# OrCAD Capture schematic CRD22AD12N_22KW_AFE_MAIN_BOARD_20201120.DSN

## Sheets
1 P1 Input and EMI filter: size A2; title: 22kW Three Phase Bi-directional AFE ACDC Main Board; rev: 0v1; note: P/N: CRD22AD12N
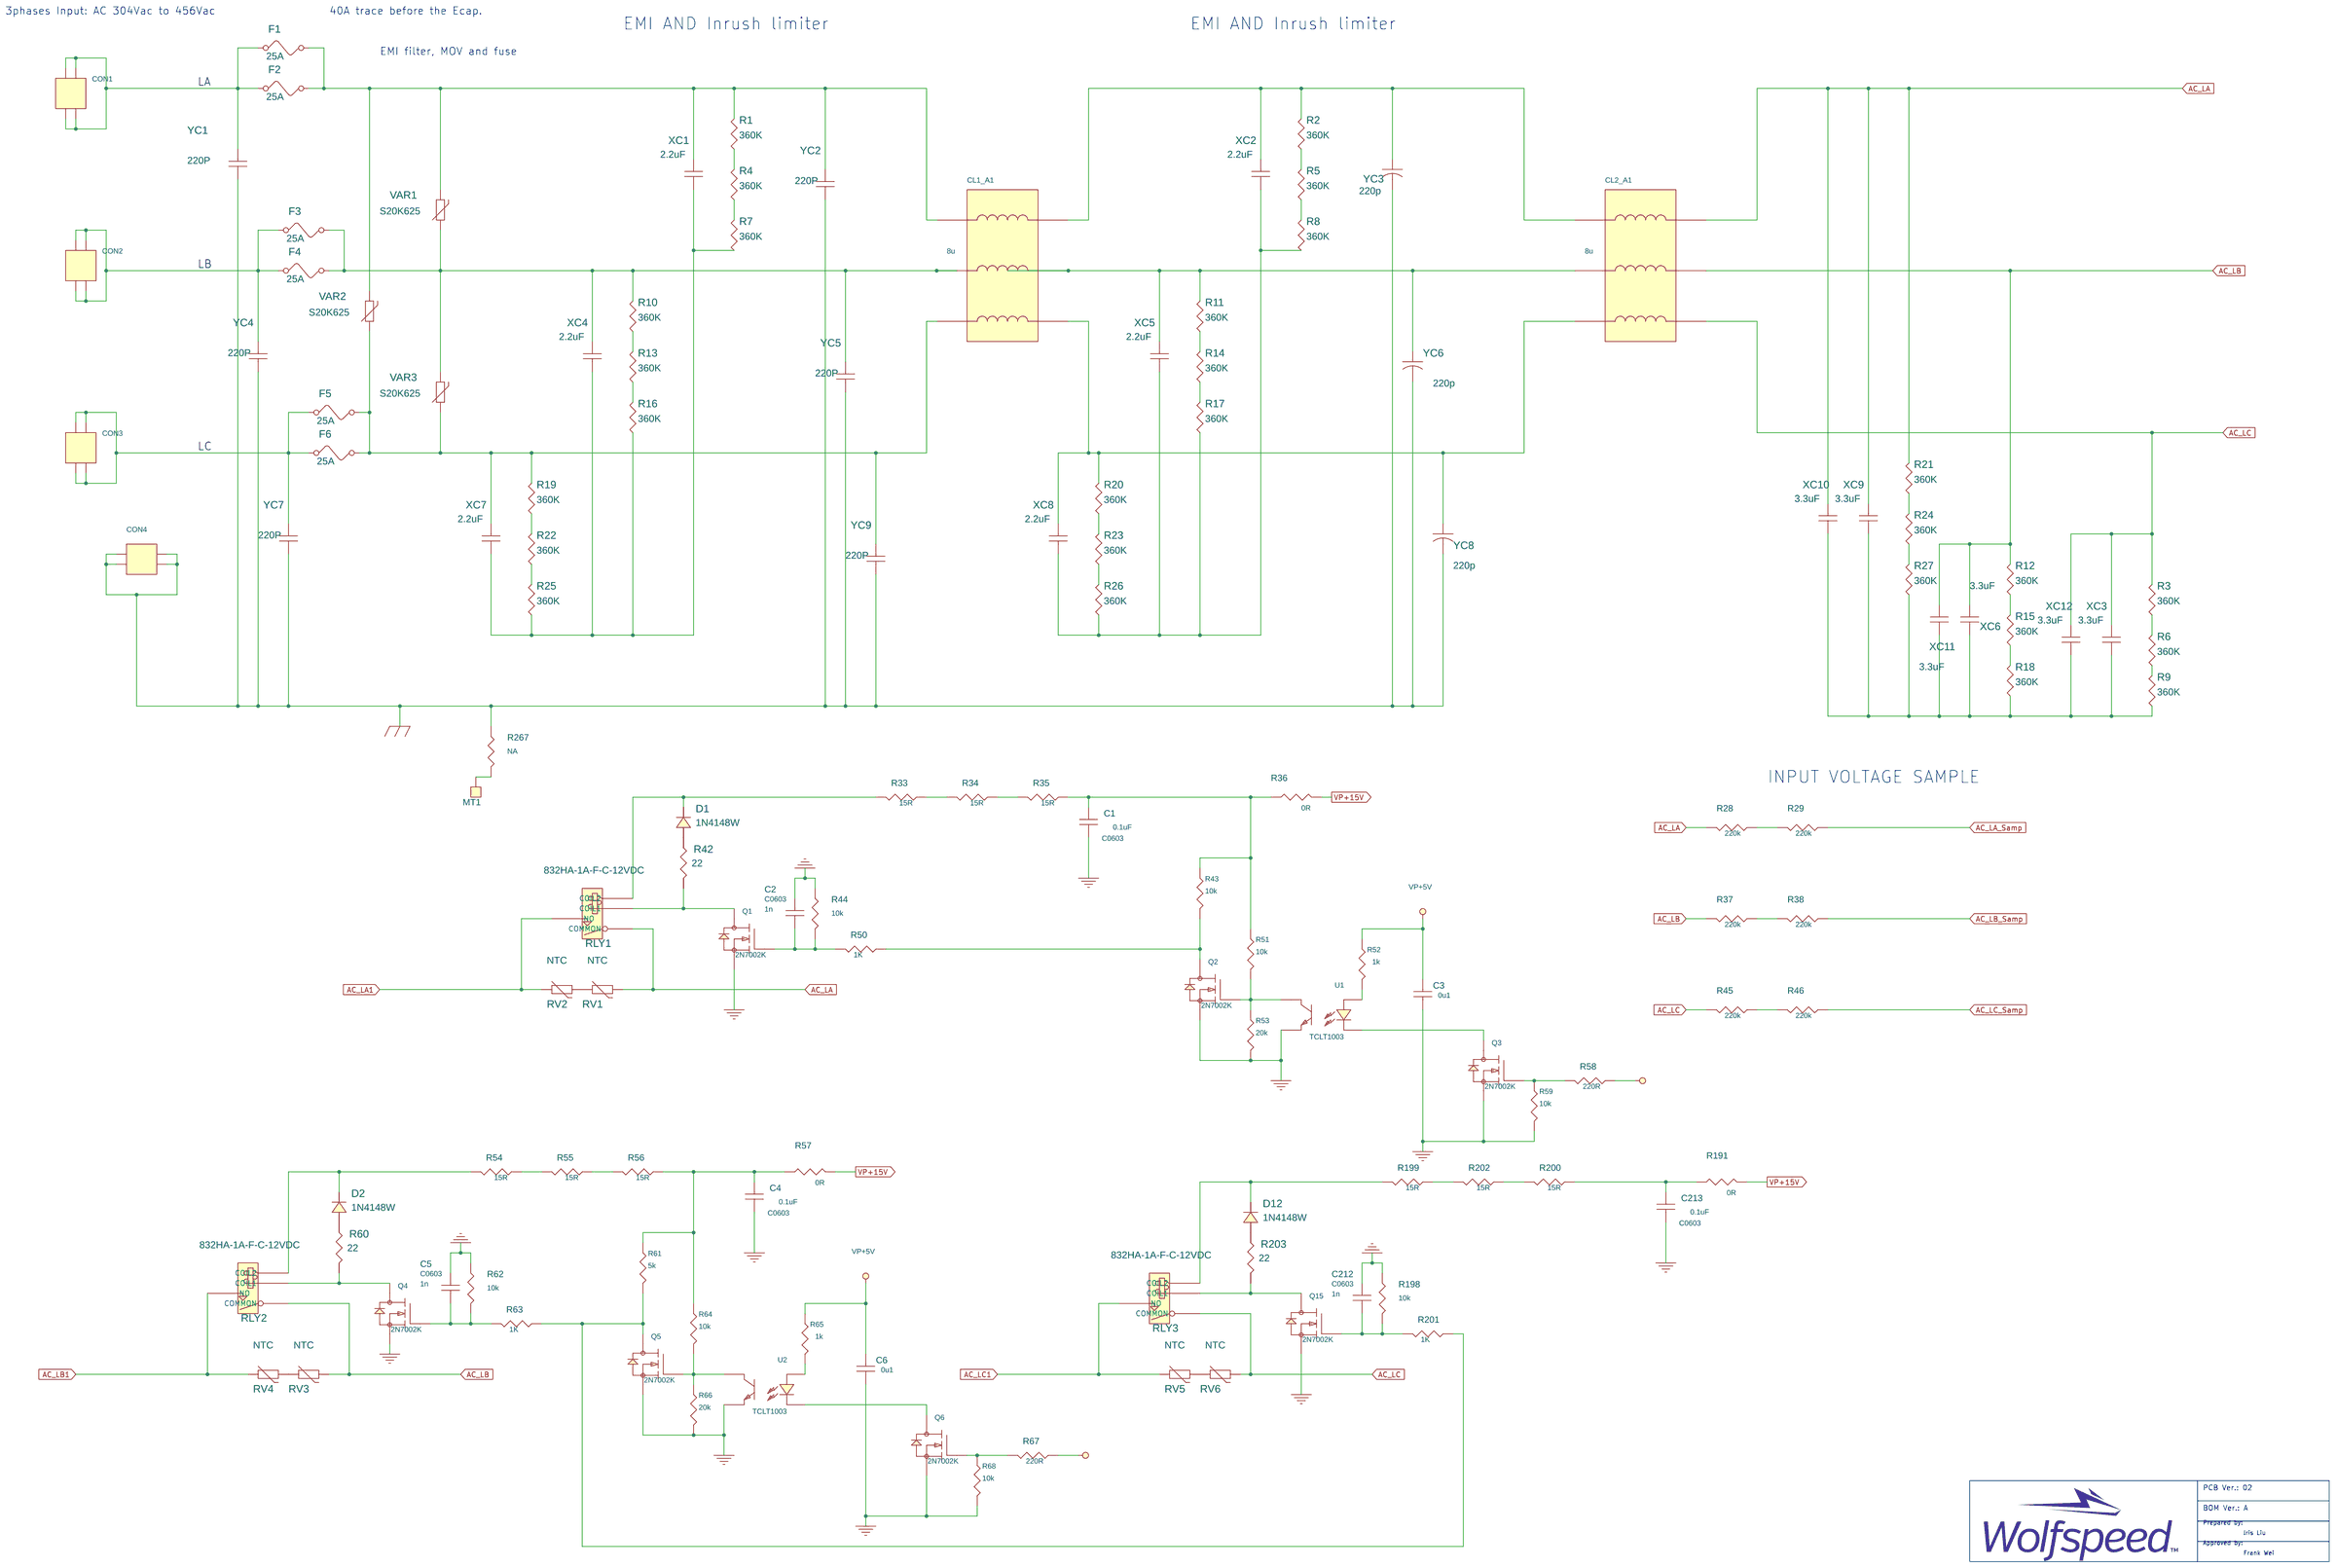
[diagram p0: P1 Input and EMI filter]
2 P2 PFC: size A2
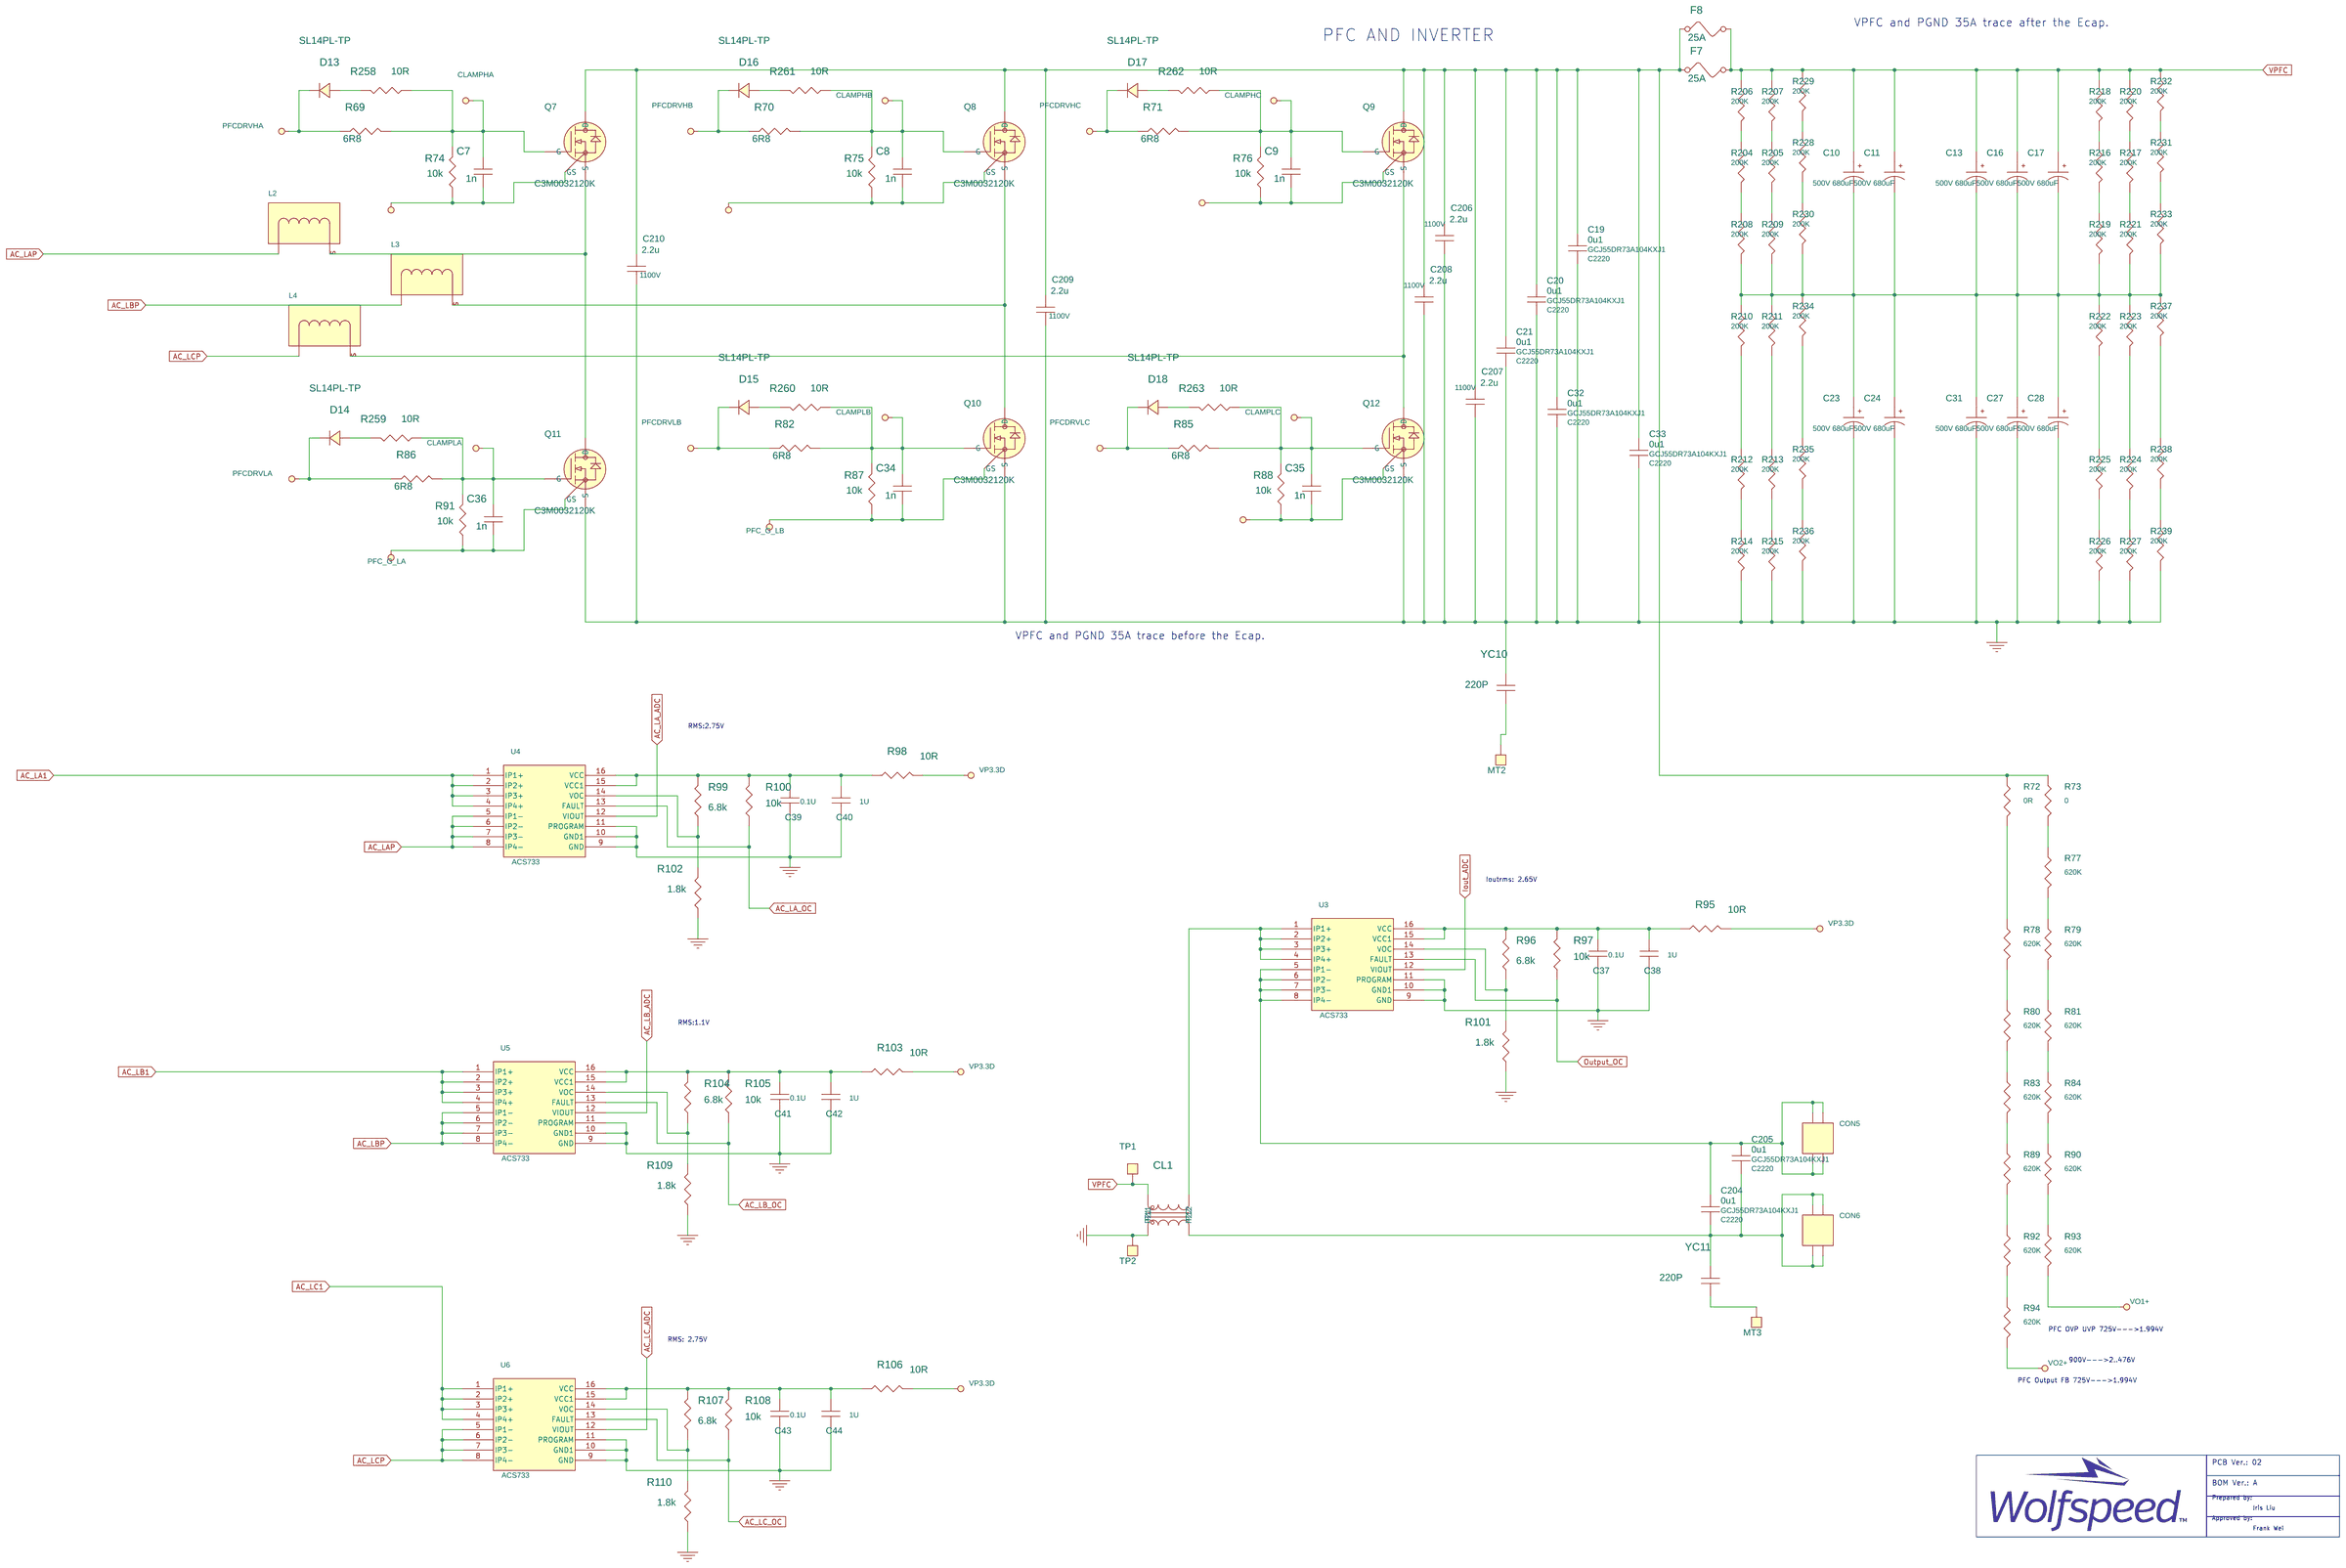
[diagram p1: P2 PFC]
3 P3 Bias POWER SUPPLY: size A1
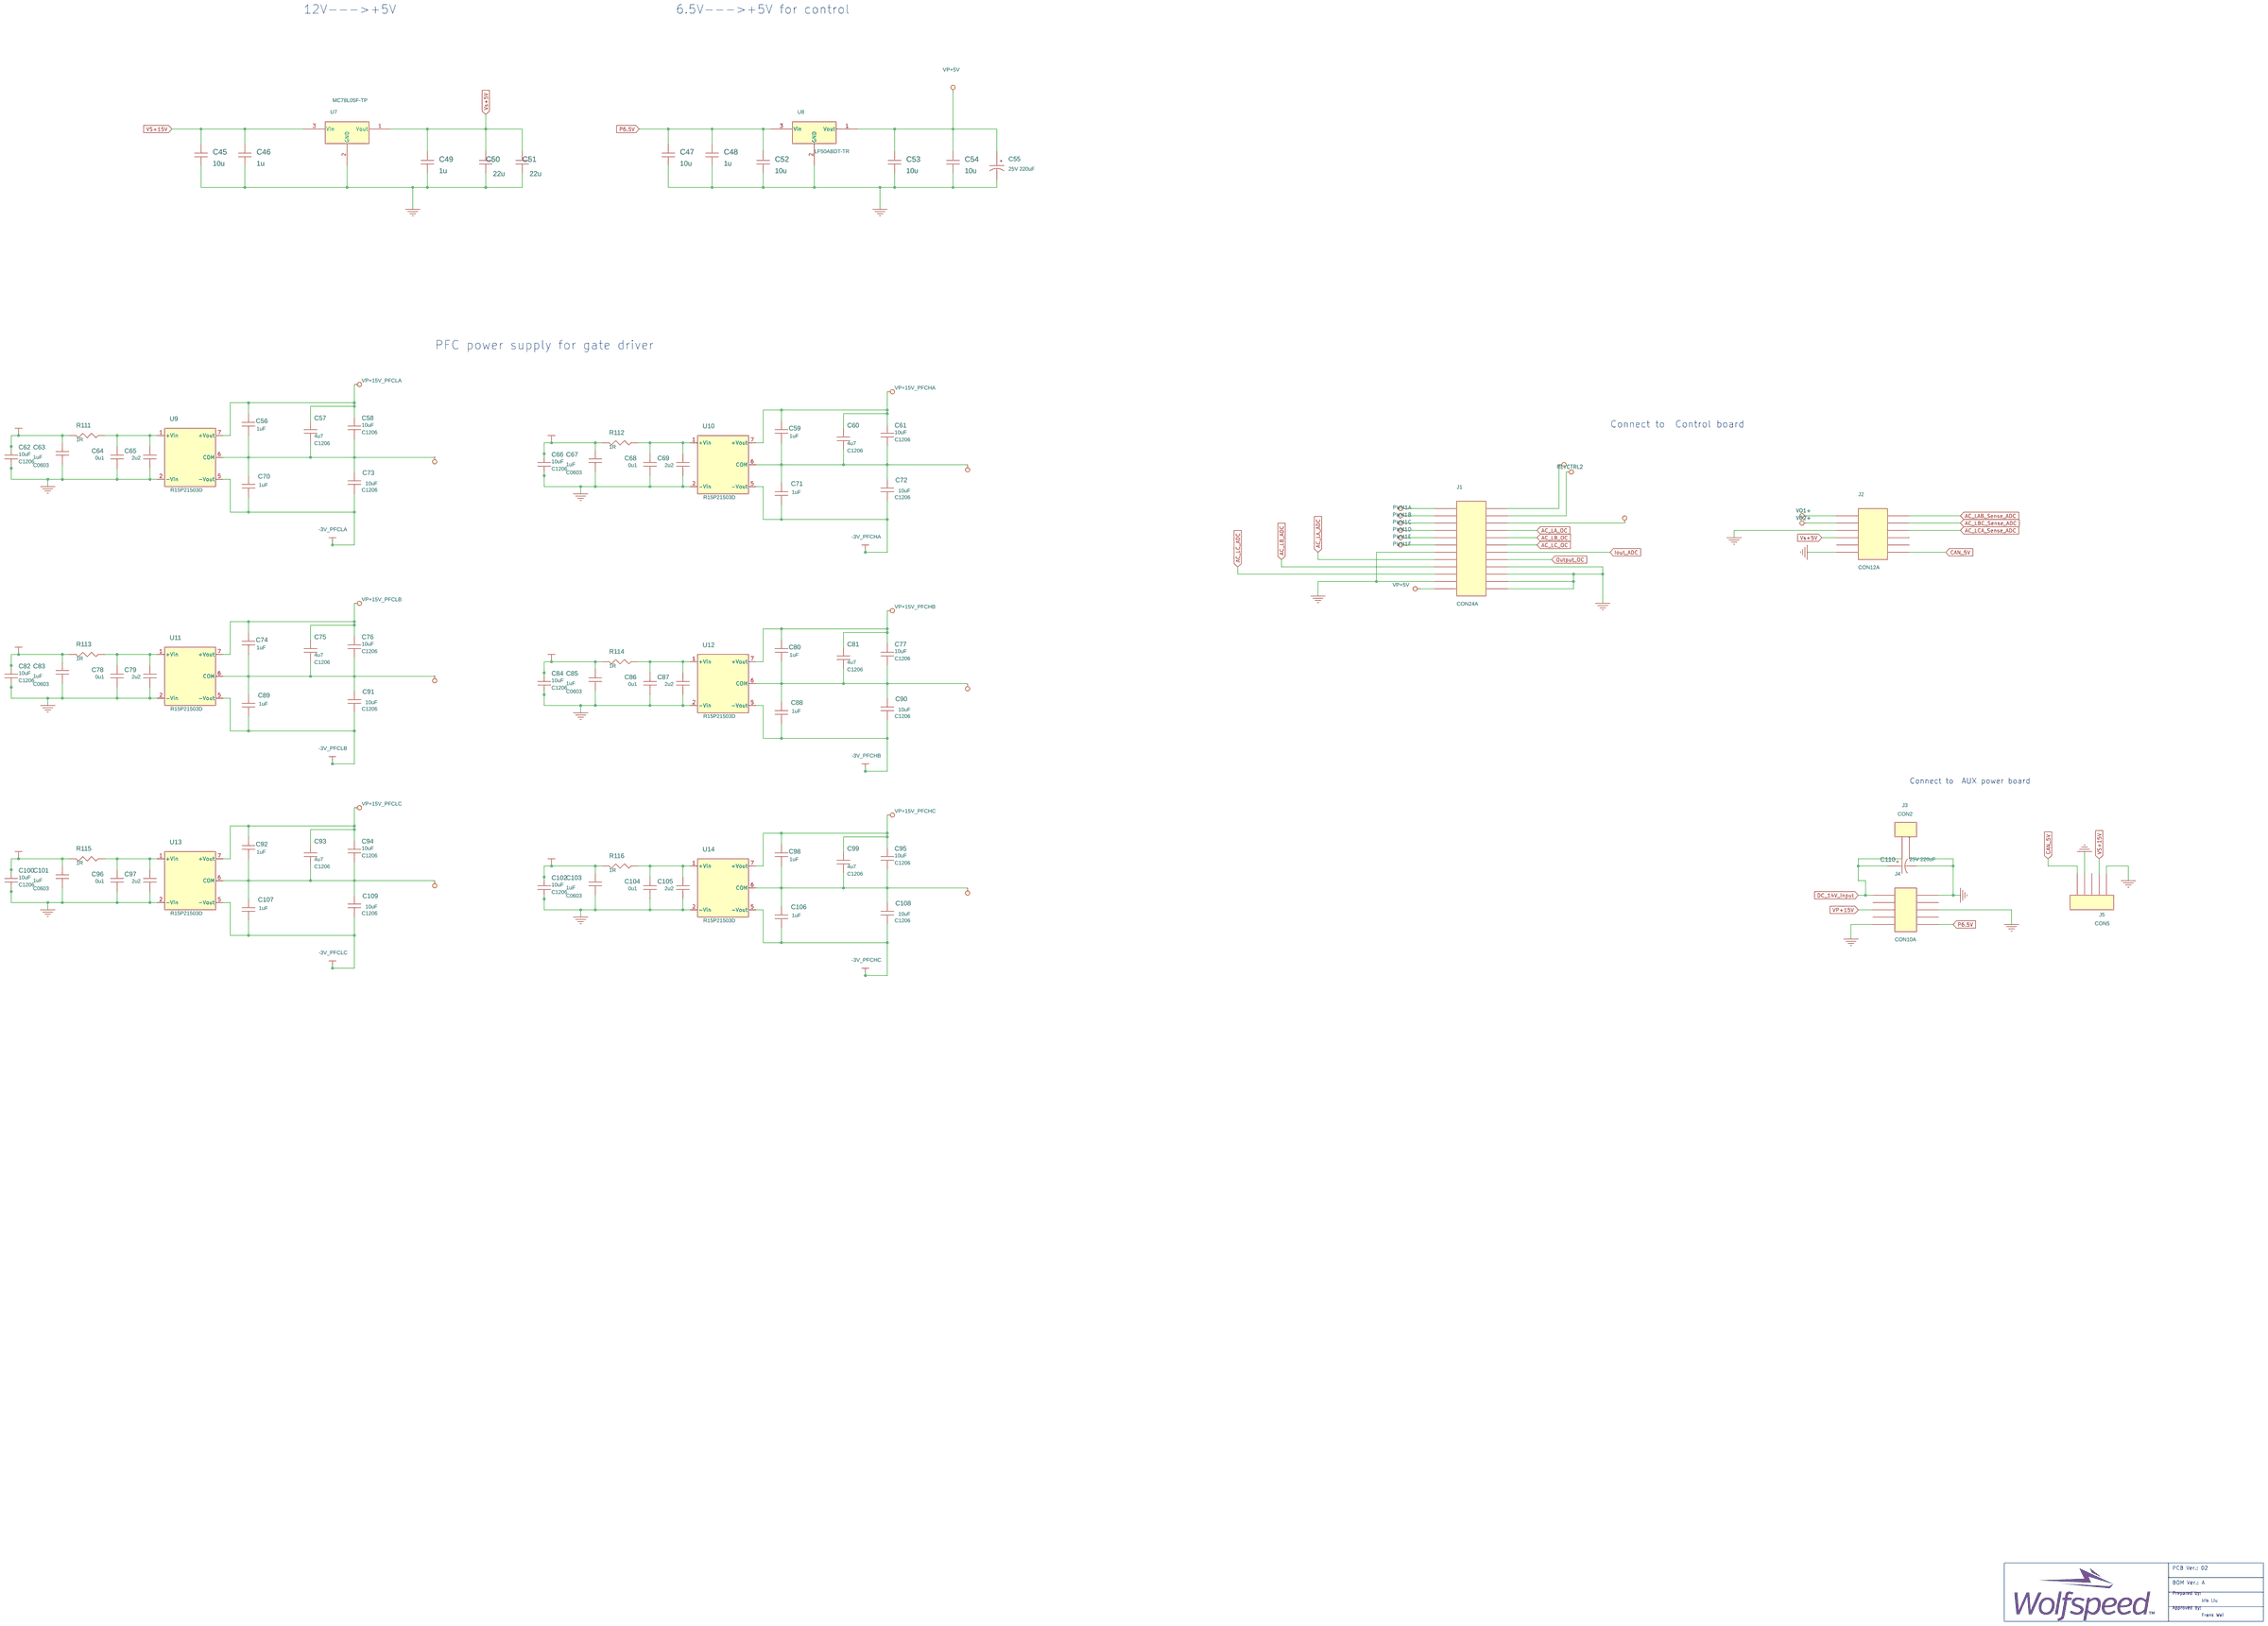
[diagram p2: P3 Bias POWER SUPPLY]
4 P4 PFC Gate Driver: size A2
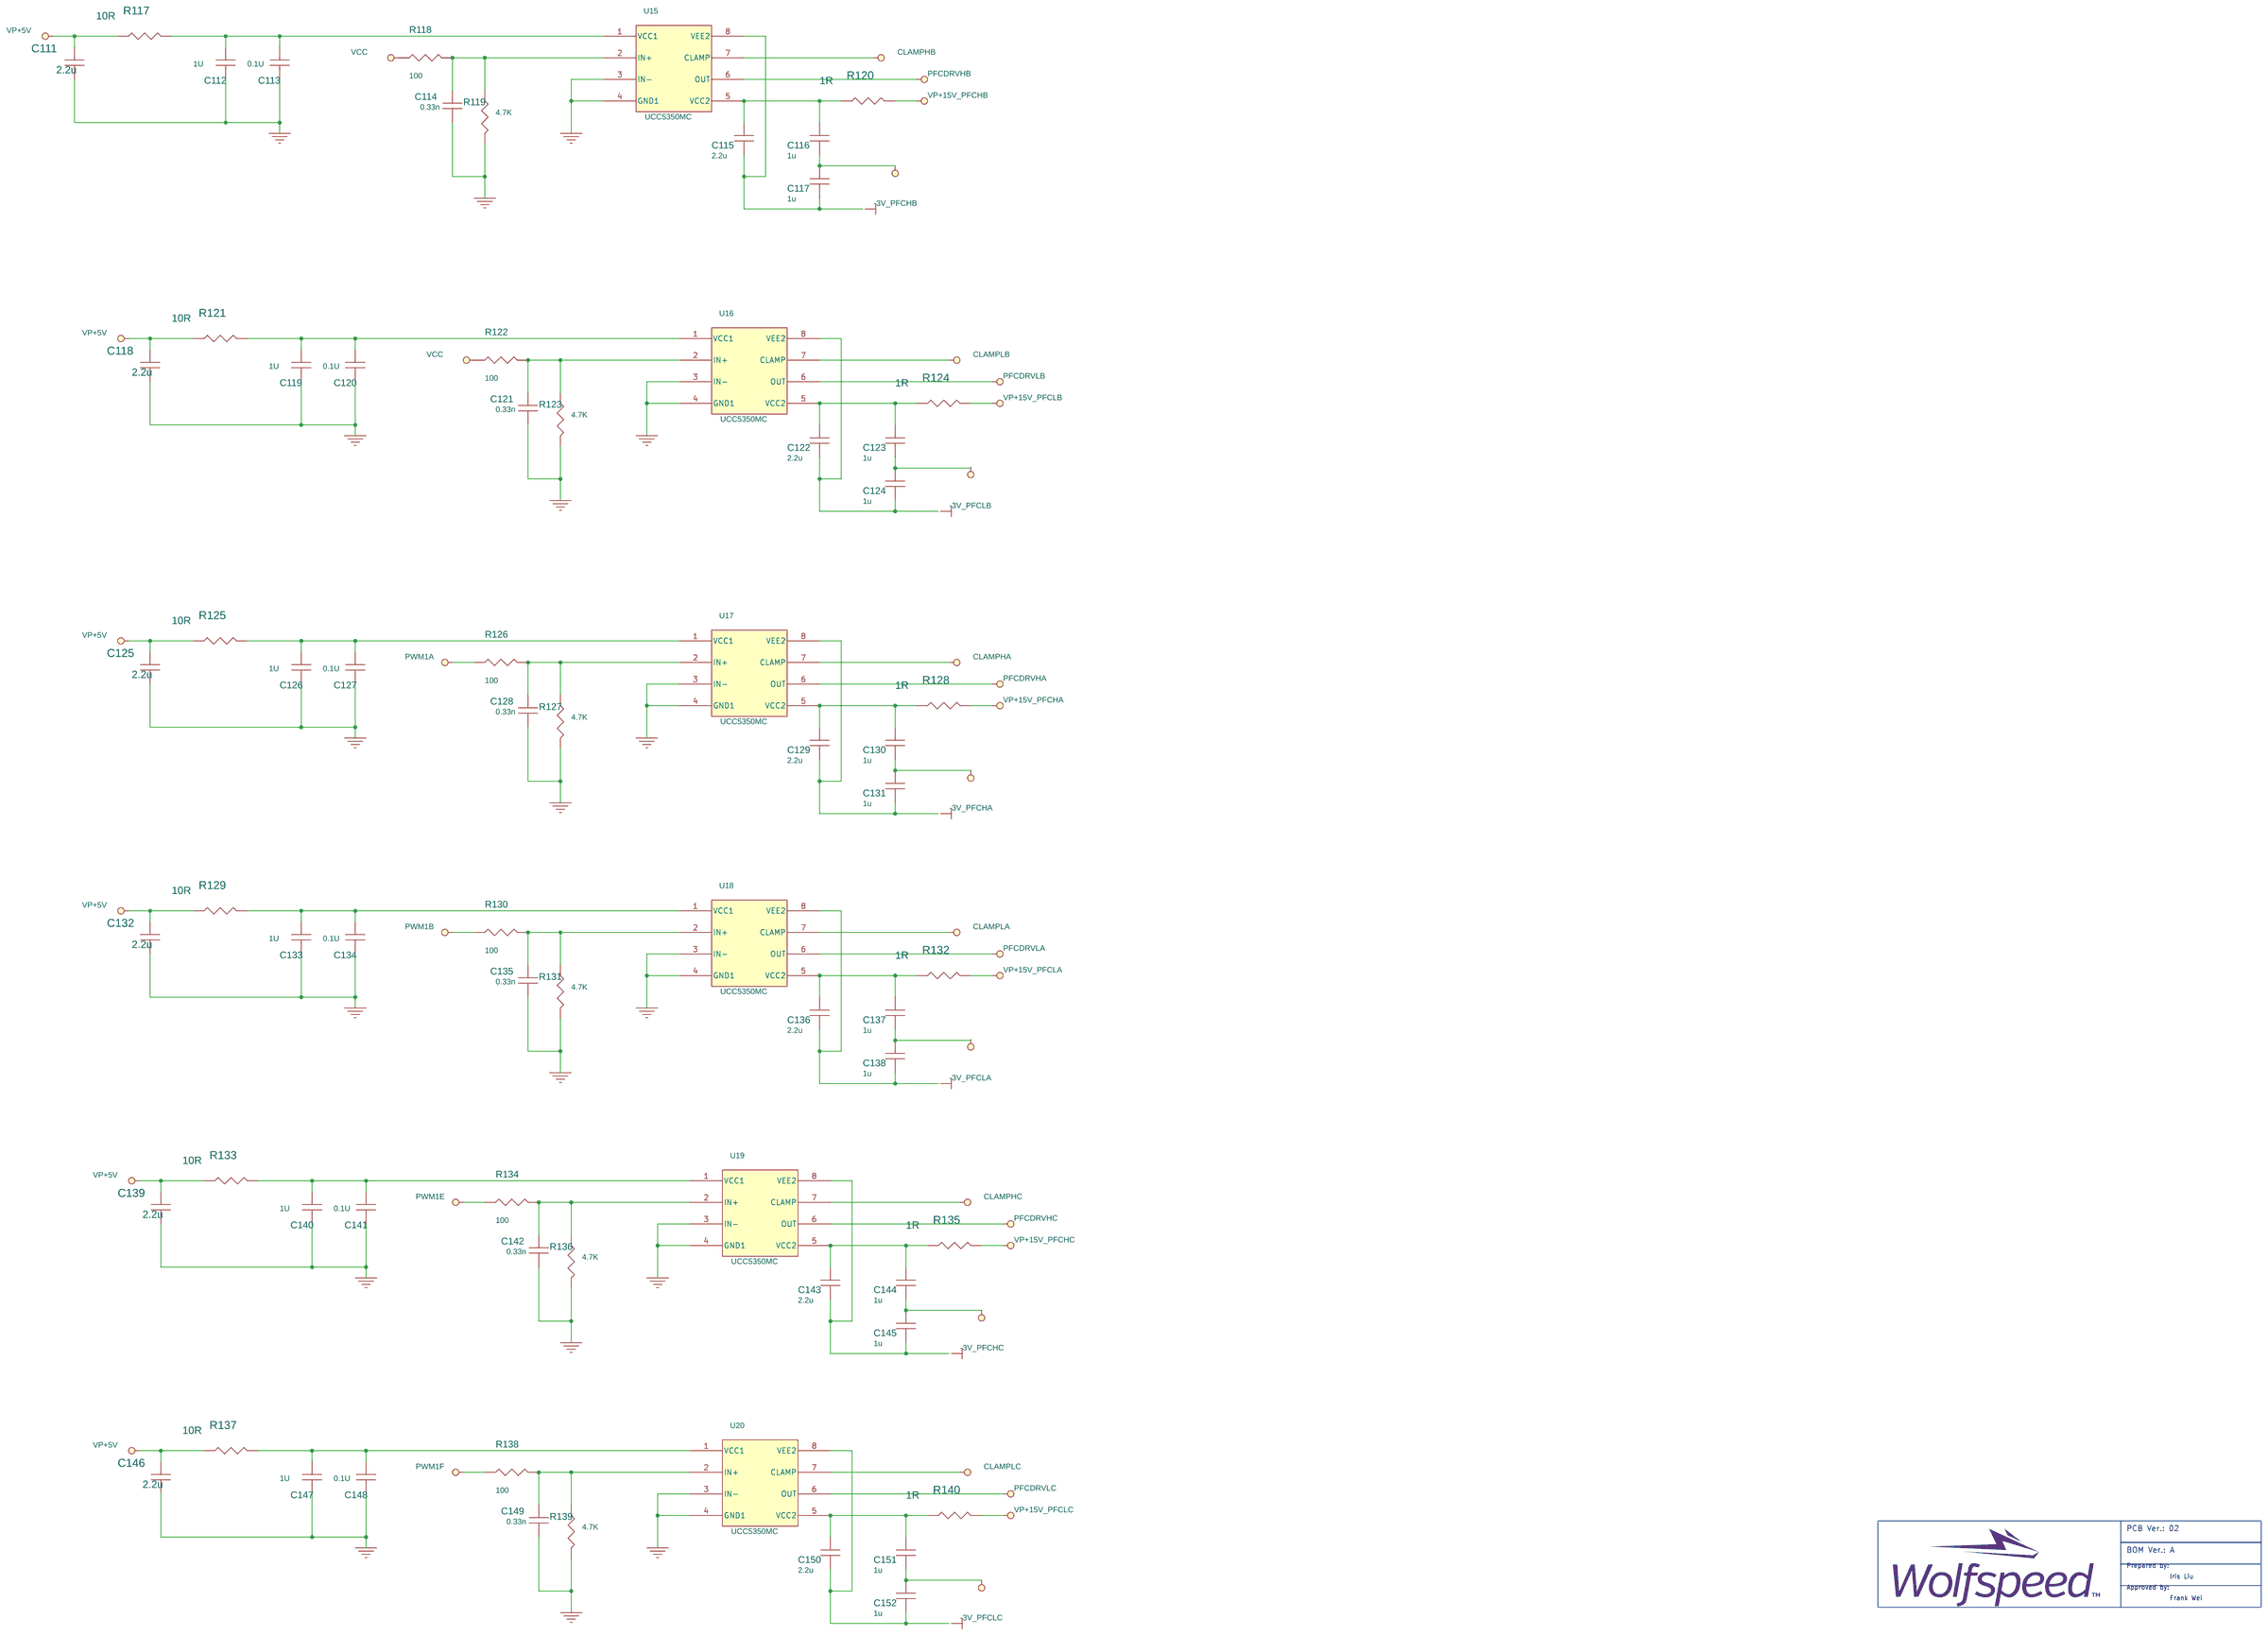
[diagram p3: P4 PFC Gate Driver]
5 P5 PFC sampling: size A3
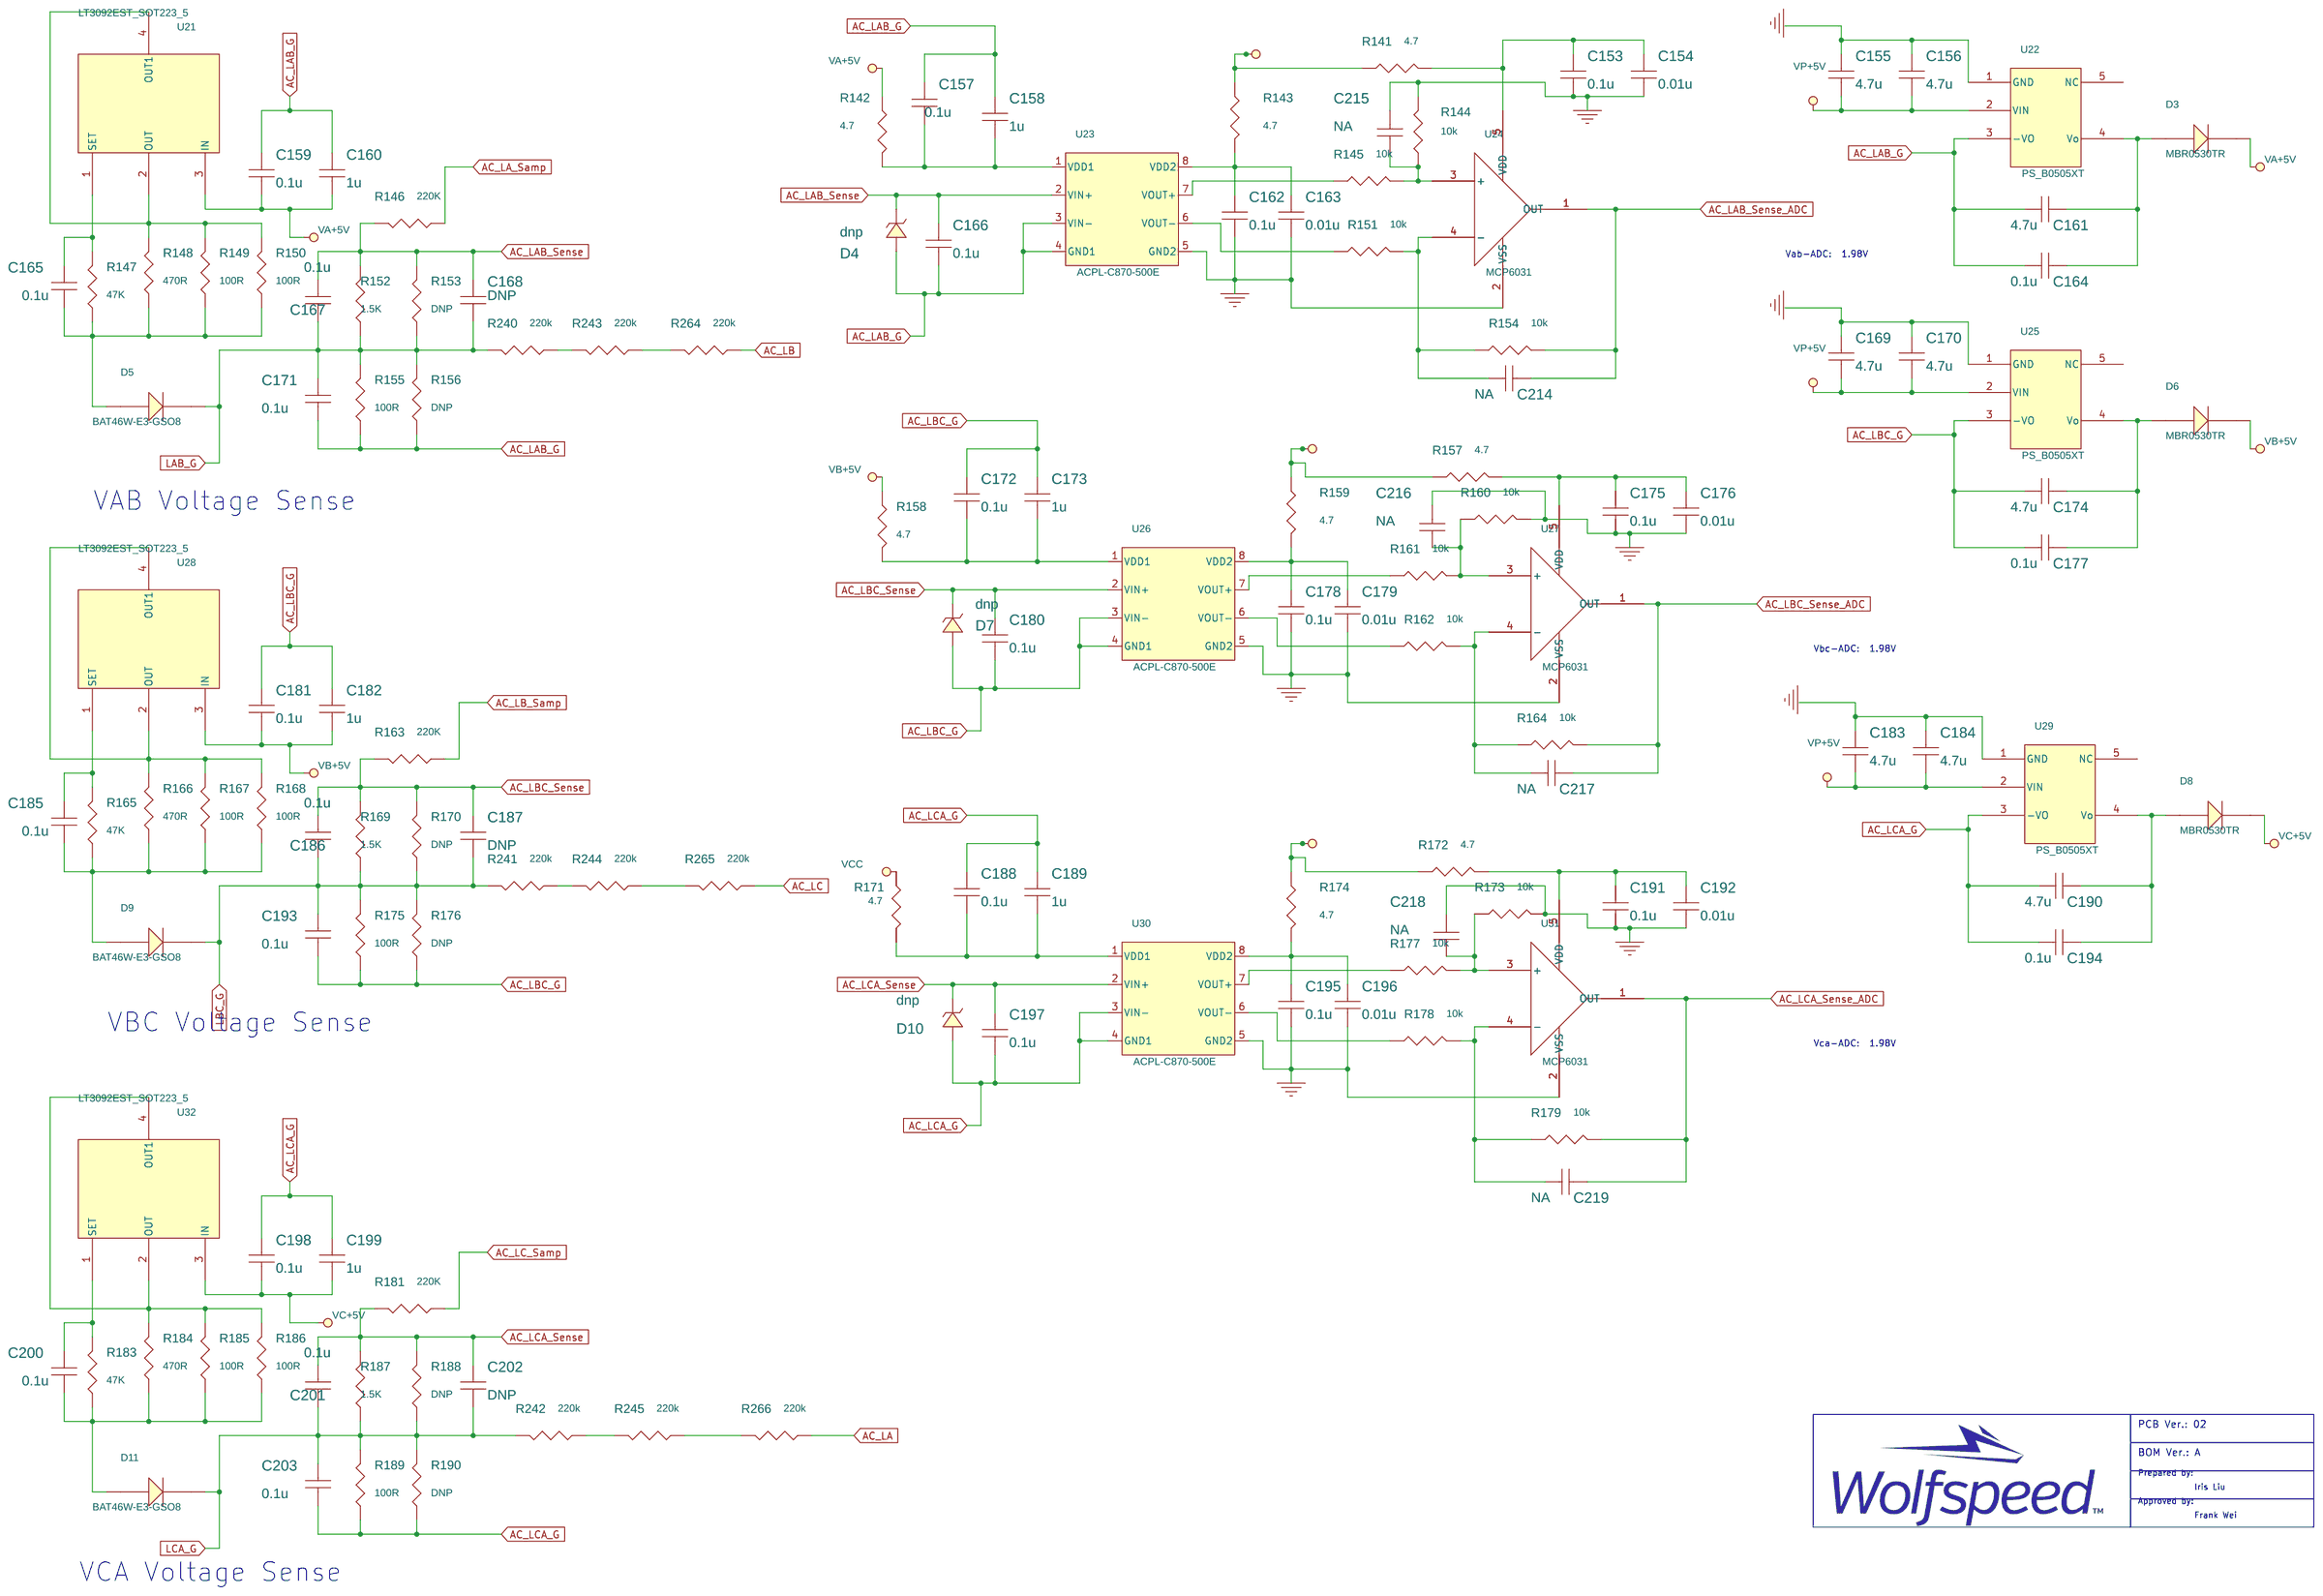
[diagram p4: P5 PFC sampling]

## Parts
sheet P1 Input and EMI filter
C1  0.1uF  [C0603]
C2  1n  [C0603]
C3  0u1  [C0603]
C4  0.1uF  [C0603]
C5  1n  [C0603]
C6  0u1  [C0603]
C212  1n  [C0603]
C213  0.1uF  [C0603]
CL1_A1  8u  [LCM1]
CL2_A1  8u  [LCM1]
CON1  Connecter  [thread4_9p9x5_1110x920]
CON2  Connecter  [thread4_9p9x5_1110x920]
CON3  Connecter  [thread4_9p9x5_1110x920]
CON4  Connecter  [thread4_9p9x5_1110x920]
D1  1N4148W  [SOD-123]
D2  1N4148W  [SOD-123]
D12  1N4148W  [SOD-123]
F1  25A  [FULSE]
F2  25A  [FULSE]
F3  25A  [FULSE]
F4  25A  [FULSE]
F5  25A  [FULSE]
F6  25A  [FULSE]
MT1  T1T2  [MTH122]
Q1  2N7002K  [SOT-23]
Q2  2N7002K  [SOT-23]
Q3  2N7002K  [SOT-23]
Q4  2N7002K  [SOT-23]
Q5  2N7002K  [SOT-23]
Q6  2N7002K  [SOT-23]
Q15  2N7002K  [SOT-23]
R1  360K  [R1206]
R2  360K  [R1206]
R3  360K  [R1206]
R4  360K  [R1206]
R5  360K  [R1206]
R6  360K  [R1206]
R7  360K  [R1206]
R8  360K  [R1206]
R9  360K  [R1206]
R10  360K  [R1206]
R11  360K  [R1206]
R12  360K  [R1206]
R13  360K  [R1206]
R14  360K  [R1206]
R15  360K  [R1206]
R16  360K  [R1206]
R17  360K  [R1206]
R18  360K  [R1206]
R19  360K  [R1206]
R20  360K  [R1206]
R21  360K  [R1206]
R22  360K  [R1206]
R23  360K  [R1206]
R24  360K  [R1206]
R25  360K  [R1206]
R26  360K  [R1206]
R27  360K  [R1206]
R28  220k  [R1206]
R29  220k  [R1206]
R33  15R  [R1206]
R34  15R  [R1206]
R35  15R  [R1206]
R36  0R  [R0603]
R37  220k  [R1206]
R38  220k  [R1206]
R42  22  [R1206]
R43  10k  [R0603]
R44  10k  [R0603]
R45  220k  [R1206]
R46  220k  [R1206]
R50  1K  [R0603]
R51  10k  [R0603]
R52  1k  [R0603]
R53  20k  [R0603]
R54  15R  [R1206]
R55  15R  [R1206]
R56  15R  [R1206]
R57  0R  [R0603]
R58  220R  [R0603]
R59  10k  [R0603]
R60  22  [R1206]
R61  5k  [R0603]
R62  10k  [R0603]
R63  1K  [R0603]
R64  10k  [R0603]
R65  1k  [R0603]
R66  20k  [R0603]
R67  220R  [R0603]
R68  10k  [R0603]
R191  0R  [R0603]
R198  10k  [R0603]
R199  15R  [R1206]
R200  15R  [R1206]
R201  1K  [R0603]
R202  15R  [R1206]
R203  22  [R1206]
R267  NA  [R1206]
RLY1  832HA-1A-F-C-12VDC  [T9SV1K15-12]
RLY2  832HA-1A-F-C-12VDC  [T9SV1K15-12]
RLY3  832HA-1A-F-C-12VDC  [T9SV1K15-12]
RV1  NTC  [NTC_od20MM]
RV2  NTC  [NTC_od20MM]
RV3  NTC  [NTC_od20MM]
RV4  NTC  [NTC_od20MM]
RV5  NTC  [NTC_od20MM]
RV6  NTC  [NTC_od20MM]
U1  TCLT1003  [tclt1003]
U2  TCLT1003  [tclt1003]
VAR1  S20K625  [MOV_OD21P5MM_PI10MM_PINV3P3MM]
VAR2  S20K625  [MOV_OD21P5MM_PI10MM_PINV3P3MM]
VAR3  S20K625  [MOV_OD21P5MM_PI10MM_PINV3P3MM]
XC1  2.2uF  [CAPFILM_26_5X12MM]
XC2  2.2uF  [CAPFILM_26_5X12MM]
XC3  3.3uF  [CAPFILM_26_5X15MM]
XC4  2.2uF  [CAPFILM_26_5X12MM]
XC5  2.2uF  [CAPFILM_26_5X12MM]
XC6  3.3uF  [CAPFILM_26_5X15MM]
XC7  2.2uF  [CAPFILM_26_5X12MM]
XC8  2.2uF  [CAPFILM_26_5X12MM]
XC9  3.3uF  [CAPFILM_26_5X15MM]
XC10  3.3uF  [CAPFILM_26_5X15MM]
XC11  3.3uF  [CAPFILM_26_5X15MM]
XC12  3.3uF  [CAPFILM_26_5X15MM]
YC1  220P  [C1812]
YC2  220P  [C1812]
YC3  220p  [C1812]
YC4  220P  [C1812]
YC5  220P  [C1812]
YC6  220p  [C1812]
YC7  220P  [C1812]
YC8  220p  [C1812]
YC9  220P  [C1812]
sheet P2 PFC
C7  1n  [C0603]
C8  1n  [C0603]
C9  1n  [C0603]
C10  500V 680uF  [ecap_d35p7_25]
C11  500V 680uF  [ecap_d35p7_25]
C13  500V 680uF  [ecap_d35p7_25]
C16  500V 680uF  [ecap_d35p7_25]
C17  500V 680uF  [ecap_d35p7_25]
C19  0u1  [C2220]
C20  0u1  [C2220]
C21  0u1  [C2220]
C23  500V 680uF  [ecap_d35p7_25]
C24  500V 680uF  [ecap_d35p7_25]
C27  500V 680uF  [ecap_d35p7_25]
C28  500V 680uF  [ecap_d35p7_25]
C31  500V 680uF  [ecap_d35p7_25]
C32  0u1  [C2220]
C33  0u1  [C2220]
C34  1n  [C0603]
C35  1n  [C0603]
C36  1n  [C0603]
C37  0.1U  [C0603]
C38  1U  [C0603]
C39  0.1U  [C0603]
C40  1U  [C0603]
C41  0.1U  [C0603]
C42  1U  [C0603]
C43  0.1U  [C0603]
C44  1U  [C0603]
C204  0u1  [C2220]
C205  0u1  [C2220]
C206  2.2u  [capfilm_31_5x12_5mm]
C207  2.2u  [capfilm_31_5x12_5mm]
C208  2.2u  [capfilm_31_5x12_5mm]
C209  2.2u  [capfilm_31_5x12_5mm]
C210  2.2u  [capfilm_31_5x12_5mm]
CL1  6Ts  [CM_4P]
CON5  Connecter  [thread4_9p9x5_1110x920]
CON6  Connecter  [thread4_9p9x5_1110x920]
D13  SL14PL-TP  [SOD-123]
D14  SL14PL-TP  [SOD-123]
D15  SL14PL-TP  [SOD-123]
D16  SL14PL-TP  [SOD-123]
D17  SL14PL-TP  [SOD-123]
D18  SL14PL-TP  [SOD-123]
F7  25A  [FULSE]
F8  25A  [FULSE]
L2  8u  [L71mm]
L3  8u  [L71mm]
L4  8u  [L71mm]
MT2  T1T2  [MTH122]
MT3  T1T2  [MTH122]
Q7  C3M0032120K  [to-247-4l]
Q8  C3M0032120K  [to-247-4l]
Q9  C3M0032120K  [to-247-4l]
Q10  C3M0032120K  [to-247-4l]
Q11  C3M0032120K  [to-247-4l]
Q12  C3M0032120K  [to-247-4l]
R69  6R8  [R1206]
R70  6R8  [R1206]
R71  6R8  [R1206]
R72  0R  [R1206]
R73  0  [R1206]
R74  10k  [R0603]
R75  10k  [R0603]
R76  10k  [R0603]
R77  620K  [R1206]
R78  620K  [R1206]
R79  620K  [R1206]
R80  620K  [R1206]
R81  620K  [R1206]
R82  6R8  [R1206]
R83  620K  [R1206]
R84  620K  [R1206]
R85  6R8  [R1206]
R86  6R8  [R1206]
R87  10k  [R0603]
R88  10k  [R0603]
R89  620K  [R1206]
R90  620K  [R1206]
R91  10k  [R0603]
R92  620K  [R1206]
R93  620K  [R1206]
R94  620K  [R1206]
R95  10R  [R0603]
R96  6.8k  [R0603]
R97  10k  [R0603]
R98  10R  [R0603]
R99  6.8k  [R0603]
R100  10k  [R0603]
R101  1.8k  [R0603]
R102  1.8k  [R0603]
R103  10R  [R0603]
R104  6.8k  [R0603]
R105  10k  [R0603]
R106  10R  [R0603]
R107  6.8k  [R0603]
R108  10k  [R0603]
R109  1.8k  [R0603]
R110  1.8k  [R0603]
R204  200K  [R1206]
R205  200K  [R1206]
R206  200K  [R1206]
R207  200K  [R1206]
R208  200K  [R1206]
R209  200K  [R1206]
R210  200K  [R1206]
R211  200K  [R1206]
R212  200K  [R1206]
R213  200K  [R1206]
R214  200K  [R1206]
R215  200K  [R1206]
R216  200K  [R1206]
R217  200K  [R1206]
R218  200K  [R1206]
R219  200K  [R1206]
R220  200K  [R1206]
R221  200K  [R1206]
R222  200K  [R1206]
R223  200K  [R1206]
R224  200K  [R1206]
R225  200K  [R1206]
R226  200K  [R1206]
R227  200K  [R1206]
R228  200K  [R1206]
R229  200K  [R1206]
R230  200K  [R1206]
R231  200K  [R1206]
R232  200K  [R1206]
R233  200K  [R1206]
R234  200K  [R1206]
R235  200K  [R1206]
R236  200K  [R1206]
R237  200K  [R1206]
R238  200K  [R1206]
R239  200K  [R1206]
R258  10R  [R1206]
R259  10R  [R1206]
R260  10R  [R1206]
R261  10R  [R1206]
R262  10R  [R1206]
R263  10R  [R1206]
TP1  T1T2  [TH47_CR98]
TP2  T1T2  [TH47_CR98]
U3  ACS733  [SOICW-16]
U4  ACS733  [SOICW-16]
U5  ACS733  [SOICW-16]
U6  ACS733  [SOICW-16]
YC10  220P  [C1812]
YC11  220P  [C1812]
sheet P3 Bias POWER SUPPLY
C45  10u  [C1206]
C46  1u  [C0603]
C47  10u  [C1206]
C48  1u  [C0603]
C49  1u  [C1206]
C50  22u  [C1206]
C51  22u  [C1206]
C52  10u  [C1206]
C53  10u  [C1206]
C54  10u  [C1206]
C55  25V 220uF  [ecap_d8p3_5]
C56  1uF  [C0603]
C57  4u7  [C1206]
C58  10uF  [C1206]
C59  1uF  [C0603]
C60  4u7  [C1206]
C61  10uF  [C1206]
C62  10uF  [C1206]
C63  1uF  [C0603]
C64  0u1  [C0603]
C65  2u2  [C1206]
C66  10uF  [C1206]
C67  1uF  [C0603]
C68  0u1  [C0603]
C69  2u2  [C1206]
C70  1uF  [C0603]
C71  1uF  [C0603]
C72  10uF  [C1206]
C73  10uF  [C1206]
C74  1uF  [C0603]
C75  4u7  [C1206]
C76  10uF  [C1206]
C77  10uF  [C1206]
C78  0u1  [C0603]
C79  2u2  [C1206]
C80  1uF  [C0603]
C81  4u7  [C1206]
C82  10uF  [C1206]
C83  1uF  [C0603]
C84  10uF  [C1206]
C85  1uF  [C0603]
C86  0u1  [C0603]
C87  2u2  [C1206]
C88  1uF  [C0603]
C89  1uF  [C0603]
C90  10uF  [C1206]
C91  10uF  [C1206]
C92  1uF  [C0603]
C93  4u7  [C1206]
C94  10uF  [C1206]
C95  10uF  [C1206]
C96  0u1  [C0603]
C97  2u2  [C1206]
C98  1uF  [C0603]
C99  4u7  [C1206]
C100  10uF  [C1206]
C101  1uF  [C0603]
C102  10uF  [C1206]
C103  1uF  [C0603]
C104  0u1  [C0603]
C105  2u2  [C1206]
C106  1uF  [C0603]
C107  1uF  [C0603]
C108  10uF  [C1206]
C109  10uF  [C1206]
C110  25V 220uF  [ecap_d8p3_5]
J1  CON24A  [con_2mm54_12x2]
J2  CON12A  [con_2mm54_6x2]
J3  CON2  [CON_5MM_2X1]
J4  CON10A  [con_2mm54_5x2]
J5  CON5  [con_2mm54_5x1]
R111  1R  [R0805]
R112  1R  [R0805]
R113  1R  [R0805]
R114  1R  [R0805]
R115  1R  [R0805]
R116  1R  [R0805]
U7  MC78L05F-TP  [SOT-89-3L]
U8  LF50ABDT-TR  [TO252AB]
U9  R15P21503D  [g1212s_2w11]
U10  R15P21503D  [g1212s_2w11]
U11  R15P21503D  [g1212s_2w11]
U12  R15P21503D  [g1212s_2w11]
U13  R15P21503D  [g1212s_2w11]
U14  R15P21503D  [g1212s_2w11]
sheet P4 PFC Gate Driver
C111  2.2u  [C0603]
C112  1U  [C0603]
C113  0.1U  [C0603]
C114  0.33n  [C0603]
C115  2.2u  [C0805]
C116  1u  [C0603]
C117  1u  [C0603]
C118  2.2u  [C0603]
C119  1U  [C0603]
C120  0.1U  [C0603]
C121  0.33n  [C0603]
C122  2.2u  [C0805]
C123  1u  [C0603]
C124  1u  [C0603]
C125  2.2u  [C0603]
C126  1U  [C0603]
C127  0.1U  [C0603]
C128  0.33n  [C0603]
C129  2.2u  [C0805]
C130  1u  [C0603]
C131  1u  [C0603]
C132  2.2u  [C0603]
C133  1U  [C0603]
C134  0.1U  [C0603]
C135  0.33n  [C0603]
C136  2.2u  [C0805]
C137  1u  [C0603]
C138  1u  [C0603]
C139  2.2u  [C0603]
C140  1U  [C0603]
C141  0.1U  [C0603]
C142  0.33n  [C0603]
C143  2.2u  [C0805]
C144  1u  [C0603]
C145  1u  [C0603]
C146  2.2u  [C0603]
C147  1U  [C0603]
C148  0.1U  [C0603]
C149  0.33n  [C0603]
C150  2.2u  [C0805]
C151  1u  [C0603]
C152  1u  [C0603]
R117  10R  [R0603]
R118  100  [R0603]
R119  4.7K  [R0603]
R120  1R  [R0805]
R121  10R  [R0603]
R122  100  [R0603]
R123  4.7K  [R0603]
R124  1R  [R0805]
R125  10R  [R0603]
R126  100  [R0603]
R127  4.7K  [R0603]
R128  1R  [R0805]
R129  10R  [R0603]
R130  100  [R0603]
R131  4.7K  [R0603]
R132  1R  [R0805]
R133  10R  [R0603]
R134  100  [R0603]
R135  1R  [R0805]
R136  4.7K  [R0603]
R137  10R  [R0603]
R138  100  [R0603]
R139  4.7K  [R0603]
R140  1R  [R0805]
U15  UCC5350MC  [SOIC8_DWV]
U16  UCC5350MC  [SOIC8_DWV]
U17  UCC5350MC  [SOIC8_DWV]
U18  UCC5350MC  [SOIC8_DWV]
U19  UCC5350MC  [SOIC8_DWV]
U20  UCC5350MC  [SOIC8_DWV]
sheet P5 PFC sampling
C153  0.1u  [C0603]
C154  0.01u  [C0603]
C155  4.7u  [C0805]
C156  4.7u  [C0805]
C157  0.1u  [C0603]
C158  1u  [C0603]
C159  0.1u  [C0603]
C160  1u  [C0603]
C161  4.7u  [C0805]
C162  0.1u  [C0603]
C163  0.01u  [C0603]
C164  0.1u  [C0603]
C165  0.1u  [C0603]
C166  0.1u  [C0603]
C167  0.1u  [C0603]
C168  DNP  [C0603]
C169  4.7u  [C0805]
C170  4.7u  [C0805]
C171  0.1u  [C0603]
C172  0.1u  [C0603]
C173  1u  [C0603]
C174  4.7u  [C0805]
C175  0.1u  [C0603]
C176  0.01u  [C0603]
C177  0.1u  [C0603]
C178  0.1u  [C0603]
C179  0.01u  [C0603]
C180  0.1u  [C0603]
C181  0.1u  [C0603]
C182  1u  [C0603]
C183  4.7u  [C0805]
C184  4.7u  [C0805]
C185  0.1u  [C0603]
C186  0.1u  [C0603]
C187  DNP  [C0603]
C188  0.1u  [C0603]
C189  1u  [C0603]
C190  4.7u  [C0805]
C191  0.1u  [C0603]
C192  0.01u  [C0603]
C193  0.1u  [C0603]
C194  0.1u  [C0603]
C195  0.1u  [C0603]
C196  0.01u  [C0603]
C197  0.1u  [C0603]
C198  0.1u  [C0603]
C199  1u  [C0603]
C200  0.1u  [C0603]
C201  0.1u  [C0603]
C202  DNP  [C0603]
C203  0.1u  [C0603]
C214  NA  [C0603]
C215  NA  [C0603]
C216  NA  [C0603]
C217  NA  [C0603]
C218  NA  [C0603]
C219  NA  [C0603]
D3  MBR0530TR  [SOD-123]
D4  dnp  [SOD-123]
D5  BAT46W-E3-GSO8  [SOD-123]
D6  MBR0530TR  [SOD-123]
D7  dnp  [SOD-123]
D8  MBR0530TR  [SOD-123]
D9  BAT46W-E3-GSO8  [SOD-123]
D10  dnp  [SOD-123]
D11  BAT46W-E3-GSO8  [SOD-123]
R141  4.7  [R0603]
R142  4.7  [R0603]
R143  4.7  [R0603]
R144  10k  [R0603]
R145  10k  [R0603]
R146  220K  [R1206]
R147  47K  [R0603]
R148  470R  [R0603]
R149  100R  [R0603]
R150  100R  [R0603]
R151  10k  [R0603]
R152  1.5K  [R1206]
R153  DNP  [R0603]
R154  10k  [R0603]
R155  100R  [R0603]
R156  DNP  [R0603]
R157  4.7  [R0603]
R158  4.7  [R0603]
R159  4.7  [R0603]
R160  10k  [R0603]
R161  10k  [R0603]
R162  10k  [R0603]
R163  220K  [R1206]
R164  10k  [R0603]
R165  47K  [R0603]
R166  470R  [R0603]
R167  100R  [R0603]
R168  100R  [R0603]
R169  1.5K  [R1206]
R170  DNP  [R0603]
R171  4.7  [R0603]
R172  4.7  [R0603]
R173  10k  [R0603]
R174  4.7  [R0603]
R175  100R  [R0603]
R176  DNP  [R0603]
R177  10k  [R0603]
R178  10k  [R0603]
R179  10k  [R0603]
R181  220K  [R1206]
R183  47K  [R0603]
R184  470R  [R0603]
R185  100R  [R0603]
R186  100R  [R0603]
R187  1.5K  [R1206]
R188  DNP  [R0603]
R189  100R  [R0603]
R190  DNP  [R0603]
R240  220k  [R1206]
R241  220k  [R1206]
R242  220k  [R1206]
R243  220k  [R1206]
R244  220k  [R1206]
R245  220k  [R1206]
R264  220k  [R1206]
R265  220k  [R1206]
R266  220k  [R1206]
U21  LT3092EST_SOT223_5  [SOT223_3]
U22  PS_B0505XT  [SMD-5]
U23  ACPL-C870-500E  [SSO-8]
U24  MCP6031  [SOT23-5]
U25  PS_B0505XT  [SMD-5]
U26  ACPL-C870-500E  [SSO-8]
U27  MCP6031  [SOT23-5]
U28  LT3092EST_SOT223_5  [SOT223_3]
U29  PS_B0505XT  [SMD-5]
U30  ACPL-C870-500E  [SSO-8]
U31  MCP6031  [SOT23-5]
U32  LT3092EST_SOT223_5  [SOT223_3]

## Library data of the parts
C1-C9 C34-C54 C56-C109 C111-C203 C212-C219 XC1-XC12 YC1 YC2 YC4 YC5 YC7 YC9-YC11 = CAP_NP
CL1_A1 CL2_A1 = 126LNS_5
CON1-CON6 = Connecter
D1 D2 D12-D18 = DIODE_0
F1-F8 = FUSE_0
MT1-MT3 TP1 TP2 = CON1_2
Q1-Q6 Q15 = 2N7002_SOT
R1-R27 = R_2
R28 R29 R33-R38 R42-R46 R50-R68 R72 R73 R77-R81 R83 R84 R89 R90 R92-R94 R111-R116 R118 R119 R122 R123 R126 R127 R130 R131 R134 R136 R138 R139 R141-R179 R181 R183-R191 R198-R245 R264-R267 = RESISTOR
RLY1-RLY3 = RELAY_SPST_1
RV1-RV6 VAR1-VAR3 = VARISTOR
U1 U2 = LEU169_TCLT1003_SOP-4L
YC3 YC6 YC8 = CAP
C10 C11 C13 C16 C17 C23 C24 C27 C28 C31 C55 C110 = CAP_POL
C19-C21 C32 C33 C204 C205 = CAP_NP: value1: GCJ55DR73A104KXJ1
C206-C210 = CAP_NP: value1: 1100V
CL1 = TRNSFMR_67125450_0
L2-L4 = 126LNS_1
Q7-Q12 = C3M0065090J_4
R69-R71 R74-R76 R82 R85-R88 R91 R95-R110 R117 R120 R121 R124 R125 R128 R129 R132 R133 R135 R137 R140 R258-R263 = R
U3-U6 = MCR1101_0
J1 = CON24A
J2 = CON12A
J3 = CON2
J4 = CON10A
J5 = CON5
U7 U8 = MC78L05F-TP
U9-U14 = E1212S-2WR2_3
U15-U20 = UCC5350MC
D3 D5 D6 D8 D9 D11 = BAS21_SOT_1
D4 D7 D10 = DIODE_ZENER_0
U21 U28 U32 = LT3092EST_SOT223_5
U22 U25 U29 = PS_B0505XT
U23 U26 U30 = 24C16BT-I_SN_3
U24 U27 U31 = MCP6031

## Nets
-3V_PFCHA: C71.2 C72.2 C129.2 C131.2 U10.5(-Vout) U17.8(VEE2)
-3V_PFCHB: C88.2 C90.2 C115.2 C117.2 U12.5(-Vout) U15.8(VEE2)
-3V_PFCHC: C106.2 C108.2 C143.2 C145.2 U14.5(-Vout) U19.8(VEE2)
-3V_PFCLA: C70.2 C73.2 C136.2 C138.2 U9.5(-Vout) U18.8(VEE2)
-3V_PFCLB: C89.2 C91.2 C122.2 C124.2 U11.5(-Vout) U16.8(VEE2)
-3V_PFCLC: C107.2 C109.2 C150.2 C152.2 U13.5(-Vout) U20.8(VEE2)
AGND: C3.2 C6.2 C37.2 C38.2 C39.2 C40.2 C41.2 C42.2 C43.2 C44.2 C47.1 C48.1 C52.1 C53.1 C54.1 C55.2 C111.2 C112.2 C113.2 C114.2 C118.2 C119.2 C120.2 C121.2 C125.2 C126.2 C127.2 C128.2 C132.2 C133.2 C134.2 C135.2 C139.2 C140.2 C141.2 C142.2 C146.2 C147.2 C148.2 C149.2 C153.2 C154.2 C155.1 C156.1 C162.2 C163.2 C169.1 C170.1 C175.2 C176.2 C178.2 C179.2 C183.1 C184.1 C191.2 C192.2 C195.2 C196.2 C215.2 C216.2 C218.2 J1.13 J1.18 J1.20 J1.21 J1.22 J1.24 J4.9 Q3.2(SOURCE) Q6.2(SOURCE) R59.1 R68.1 R101.2 R102.2 R109.2 R110.2 R119.2 R123.2 R127.2 R131.2 R136.2 R139.2 R144.2 R160.2 R173.2 U3.9(GND) U3.10(GND1) U3.11(PROGRAM) U4.9(GND) U4.10(GND1) U4.11(PROGRAM) U5.9(GND) U5.10(GND1) U5.11(PROGRAM) U6.9(GND) U6.10(GND1) U6.11(PROGRAM) U8.2(GND) U15.3(IN-) U15.4(GND1) U16.3(IN-) U16.4(GND1) U17.3(IN-) U17.4(GND1) U18.3(IN-) U18.4(GND1) U19.3(IN-) U19.4(GND1) U20.3(IN-) U20.4(GND1) U22.1(GND) U23.5(GND2) U24.2(VSS) U25.1(GND) U26.5(GND2) U27.2(VSS) U29.1(GND) U30.5(GND2) U31.2(VSS)
GND_EARTH: CON4.1 CON4.2 CON4.3 CON4.4 R267.1 YC1.2 YC2.2 YC3.2 YC4.2 YC5.2 YC6.2 YC7.2 YC8.2 YC9.2
P6.5V: C47.2 C48.2 C52.2 J4.10 U8.3(Vin)
PGND: C19.2 C20.2 C21.2 C23.2 C24.2 C27.2 C28.2 C31.2 C32.2 C33.2 C45.1 C46.1 C49.1 C50.1 C51.1 C206.2 C207.2 C208.2 C209.2 C210.2 CL1.2(P21) J2.5 J5.5 Q10.2(S) Q11.2(S) Q12.2(S) R214.1 R215.1 R226.1 R227.1 R236.1 R239.1 TP2.1 U7.2(GND) YC10.1
AC_LA: CL2_A1.6 R21.2 R28.1 R266.1 RLY1.3(COMMON) RV1.2 XC9.1 XC10.1
AC_LA1: RLY1.4(NO) RV2.1 U4.1(IP1+) U4.2(IP2+) U4.3(IP3+) U4.4(IP4+)
AC_LA_ADC: J1.15 U4.12(VIOUT)
AC_LA_OC: J1.8 R100.2 U4.13(FAULT)
AC_LA_Samp: R29.2 R146.1
AC_LAB_G: C157.1 C158.1 C159.1 C160.1 C161.1 C164.1 C166.2 C171.2 D4.1(ANODE) R155.1 R156.1 U22.3(-VO) U23.3(VIN-) U23.4(GND1)
AC_LAB_Sense: C166.1 C167.1 C168.1 D4.2(CATHODE) R146.2 R152.2 R153.2 U23.2(VIN+)
AC_LAB_Sense_ADC: C214.2 J2.2 R154.2 U24.1(OUT)
AC_LAP: L2.3 U4.5(IP1-) U4.6(IP2-) U4.7(IP3-) U4.8(IP4-)
AC_LB: CL2_A1.4 R12.2 R37.1 R264.1 RLY2.3(COMMON) RV3.2 XC6.1 XC11.1
AC_LB1: RLY2.4(NO) RV4.1 U5.1(IP1+) U5.2(IP2+) U5.3(IP3+) U5.4(IP4+)
AC_LB_ADC: J1.17 U5.12(VIOUT)
AC_LB_OC: J1.10 R105.2 U5.13(FAULT)
AC_LB_Samp: R38.2 R163.1
AC_LBC_G: C172.1 C173.1 C174.1 C177.1 C180.2 C181.1 C182.1 C193.2 D7.1(ANODE) R175.1 R176.1 U25.3(-VO) U26.3(VIN-) U26.4(GND1)
AC_LBC_Sense: C180.1 C186.1 C187.1 D7.2(CATHODE) R163.2 R169.2 R170.2 U26.2(VIN+)
AC_LBC_Sense_ADC: C217.2 J2.4 R164.2 U27.1(OUT)
AC_LBP: L3.3 U5.5(IP1-) U5.6(IP2-) U5.7(IP3-) U5.8(IP4-)
AC_LC: CL2_A1.2 R3.2 R45.1 R265.1 RLY3.3(COMMON) RV6.2 XC3.1 XC12.1
AC_LC1: RLY3.4(NO) RV5.1 U6.1(IP1+) U6.2(IP2+) U6.3(IP3+) U6.4(IP4+)
AC_LC_ADC: J1.19 U6.12(VIOUT)
AC_LC_OC: J1.12 R108.2 U6.13(FAULT)
AC_LC_Samp: R46.2 R181.1
AC_LCA_G: C188.1 C189.1 C190.1 C194.1 C197.2 C198.1 C199.1 C203.2 D10.1(ANODE) R189.1 R190.1 U29.3(-VO) U30.3(VIN-) U30.4(GND1)
AC_LCA_Sense: C197.1 C201.1 C202.1 D10.2(CATHODE) R181.2 R187.2 R188.2 U30.2(VIN+)
AC_LCA_Sense_ADC: C219.2 J2.6 R179.2 U31.1(OUT)
AC_LCP: L4.3 U6.5(IP1-) U6.6(IP2-) U6.7(IP3-) U6.8(IP4-)
CAN5V_GND: J2.11 J5.2
CAN_5V: J2.12 J5.1
ClampHA: C7.1 Q7.4(G) R69.2 R74.2 R258.1 U17.7(CLAMP)
ClampHB: C8.1 Q8.4(G) R70.2 R75.2 R261.1 U15.7(CLAMP)
ClampHC: C9.1 Q9.4(G) R71.2 R76.2 R262.1 U19.7(CLAMP)
ClampLA: C36.1 Q11.4(G) R86.2 R91.2 R259.1 U18.7(CLAMP)
ClampLB: C34.1 Q10.4(G) R82.2 R87.2 R260.1 U16.7(CLAMP)
ClampLC: C35.1 Q12.4(G) R85.2 R88.2 R263.1 U20.7(CLAMP)
DC_14V_input: C110.1 J3.2 J4.1
GGND: C1.2 C2.1 C4.2 C5.1 C62.2 C63.2 C64.2 C65.2 C66.2 C67.2 C68.2 C69.2 C78.2 C79.2 C82.2 C83.2 C84.2 C85.2 C86.2 C87.2 C96.2 C97.2 C100.2 C101.2 C102.2 C103.2 C104.2 C105.2 C212.1 C213.2 J4.6 Q1.2(SOURCE) Q2.2(SOURCE) Q4.2(SOURCE) Q5.2(SOURCE) Q15.2(SOURCE) R44.2 R53.1 R62.2 R66.1 R198.2 U1.3 U2.3 U9.2(-Vin) U10.2(-Vin) U11.2(-Vin) U12.2(-Vin) U13.2(-Vin) U14.2(-Vin)
IGND: C110.2 J3.1 J4.2
Iout_ADC: J1.14 U3.12(VIOUT)
LA: CON1.1 CON1.2 CON1.3 CON1.4 F1.1 F2.1 YC1.1
LAB_G: C167.2 C168.2 C171.1 D5.2(CATHODE) R152.1 R153.1 R155.2 R156.2 R240.2
LB: CON2.1 CON2.2 CON2.3 CON2.4 F3.1 F4.1 YC4.1
LBC_G: C186.2 C187.2 C193.1 D9.2(CATHODE) R169.1 R170.1 R175.2 R176.2 R241.2
LC: CON3.1 CON3.2 CON3.3 CON3.4 F5.1 F6.1 YC7.1
LCA_G: C201.2 C202.2 C203.1 D11.2(CATHODE) R187.1 R188.1 R189.2 R190.2 R242.2
Output_OC: J1.16 R97.2 U3.13(FAULT)
PFC_G_HA: C7.2 C59.2 C60.2 C61.2 C71.1 C72.1 C130.2 C131.1 Q7.3(GS) R74.1 U10.6(COM)
PFC_G_HB: C8.2 C77.2 C80.2 C81.2 C88.1 C90.1 C116.2 C117.1 Q8.3(GS) R75.1 U12.6(COM)
PFC_G_HC: C9.2 C95.2 C98.2 C99.2 C106.1 C108.1 C144.2 C145.1 Q9.3(GS) R76.1 U14.6(COM)
PFC_G_LA: C36.2 C56.2 C57.2 C58.2 C70.1 C73.1 C137.2 C138.1 Q11.3(GS) R91.1 U9.6(COM)
PFC_G_LB: C34.2 C74.2 C75.2 C76.2 C89.1 C91.1 C123.2 C124.1 Q10.3(GS) R87.1 U11.6(COM)
PFC_G_LC: C35.2 C92.2 C93.2 C94.2 C107.1 C109.1 C151.2 C152.1 Q12.3(GS) R88.1 U13.6(COM)
PFCDRVHA: D13.2(K) R69.1 U17.6(OUT)
PFCDRVHB: D16.2(K) R70.1 U15.6(OUT)
PFCDRVHC: D17.2(K) R71.1 U19.6(OUT)
PFCDRVLA: D14.2(K) R86.1 U18.6(OUT)
PFCDRVLB: D15.2(K) R82.1 U16.6(OUT)
PFCDRVLC: D18.2(K) R85.1 U20.6(OUT)
PWM1A: J1.1 R126.1
PWM1B: J1.3 R130.1
PWM1C: J1.5 R118.1
PWM1D: J1.7 R122.1
PWM1E: J1.9 R134.1
PWM1F: J1.11 R138.1
RLYCTRL1: J1.2 R58.2
RLYCTRL2: J1.4 R67.2
VA+5V: C159.2 C160.2 D3.2(CATHODE) R142.1 U21.3(IN)
VB+5V: C181.2 C182.2 D6.2(CATHODE) R158.1 U28.3(IN)
VC+5V: C198.2 C199.2 D8.2(CATHODE) R171.1 U32.3(IN)
VO1+: J2.1 R93.1
VO2+: J2.3 R94.1
VP3.3D: J1.6 R95.1 R98.1 R103.1 R106.1 R141.1 R143.1 R157.1 R159.1 R172.1 R174.1
VP+5V: C3.1 C6.1 C53.2 C54.2 C55.1 C111.1 C118.1 C125.1 C132.1 C139.1 C146.1 C155.2 C156.2 C169.2 C170.2 C183.2 C184.2 J1.23 R52.2 R65.2 R117.1 R121.1 R125.1 R129.1 R133.1 R137.1 U8.1(Vout) U22.2(VIN) U25.2(VIN) U29.2(VIN)
VP+15V: C62.1 C63.1 C66.1 C67.1 C82.1 C83.1 C84.1 C85.1 C100.1 C101.1 C102.1 C103.1 J4.5 R36.1 R57.1 R111.2 R112.2 R113.2 R114.2 R115.2 R116.2 R191.1
VP+15V_PFCHA: C59.1 C60.1 C61.1 R128.2 U10.7(+Vout)
VP+15V_PFCHB: C77.1 C80.1 C81.1 R120.2 U12.7(+Vout)
VP+15V_PFCHC: C95.1 C98.1 C99.1 R135.2 U14.7(+Vout)
VP+15V_PFCLA: C56.1 C57.1 C58.1 R132.2 U9.7(+Vout)
VP+15V_PFCLB: C74.1 C75.1 C76.1 R124.2 U11.7(+Vout)
VP+15V_PFCLC: C92.1 C93.1 C94.1 R140.2 U13.7(+Vout)
VPFC: C10.1 C11.1 C13.1 C16.1 C17.1 CL1.1(P11) F7.2 F8.2 R206.2 R207.2 R218.2 R220.2 R229.2 R232.2 TP1.1
Vs+5V: C49.2 C50.2 C51.2 J2.7 U7.1(Vout)
VS+15V: C45.2 C46.2 J5.4 U7.3(Vin)
N17200031: C165.1 R147.2 U21.1(SET)
N17200043: C165.2 D5.1(ANODE) R147.1 R148.1 R149.1 R150.1
N17200052: R148.2 R149.2 R150.2 U21.2(OUT) U21.4(OUT1)
N17202885: C185.1 R165.2 U28.1(SET)
N17202901: C185.2 D9.1(ANODE) R165.1 R166.1 R167.1 R168.1
N17202907: R166.2 R167.2 R168.2 U28.2(OUT) U28.4(OUT1)
N17203702: C200.1 R183.2 U32.1(SET)
N17203726: R184.2 R185.2 R186.2 U32.2(OUT) U32.4(OUT1)
N17203738: C200.2 D11.1(ANODE) R183.1 R184.1 R185.1 R186.1
N17207655: C157.2 C158.2 R142.2 U23.1(VDD1)
N17208388: C162.1 C163.1 R143.2 U23.8(VDD2)
N17208484: R145.1 U23.7(VOUT+)
N17208491: R151.1 U23.6(VOUT-)
N17208678: C214.1 R151.2 R154.1 U24.4(-)
N17208781: C153.1 C154.1 R141.2 U24.5(VDD)
N17209770: C172.2 C173.2 R158.2 U26.1(VDD1)
N17209888: C178.1 C179.1 R159.2 U26.8(VDD2)
N17209896: R161.1 U26.7(VOUT+)
N17209898: R162.1 U26.6(VOUT-)
N17209922: C216.1 R160.1 R161.2 U27.3(+)
N17209924: C217.1 R162.2 R164.1 U27.4(-)
N17209942: C175.1 C176.1 R157.2 U27.5(VDD)
N17210692: C188.2 C189.2 R171.2 U30.1(VDD1)
N17210810: C195.1 C196.1 R174.2 U30.8(VDD2)
N17210816: R177.1 U30.7(VOUT+)
N17210820: R178.1 U30.6(VOUT-)
N17210844: C218.1 R173.1 R177.2 U31.3(+)
N17210846: C219.1 R178.2 R179.1 U31.4(-)
N17210864: C191.1 C192.1 R172.2 U31.5(VDD)
N17217934: C215.1 R144.1 R145.2 U24.3(+)
N17223082: C161.2 C164.2 D3.1(ANODE) U22.4(Vo)
N17223482: C174.2 C177.2 D6.1(ANODE) U25.4(Vo)
N17224001: C190.2 C194.2 D8.1(ANODE) U29.4(Vo)
N17453218: C64.1 C65.1 R111.1 U9.1(+Vin)
N17746491: C126.1 C127.1 R125.2 U17.1(VCC1)
N17747250: C128.1 R126.2 R127.1 U17.2(IN+)
N17751858: C129.1 C130.1 R128.1 U17.5(VCC2)
N17896613: CL1_A1.1 F5.2 F6.2 R19.2 VAR2.1 VAR3.1 XC7.1 YC9.1
N17896717: R28.2 R29.1
N17896948: R7.1 R16.1 R25.1 XC1.2 XC4.2 XC7.2
N17897141: R19.1 R22.2
N17897143: R22.1 R25.2
N17898200: CL1_A1.5 F1.2 F2.2 R1.2 VAR1.2 VAR2.2 XC1.1 YC2.1
N17898311: CL1_A1.3 F3.2 F4.2 R10.2 VAR1.1 VAR3.2 XC4.1 YC5.1
N17903019: R10.1 R13.2
N17903021: R13.1 R16.2
N17903179: R1.1 R4.2
N17903181: R4.1 R7.2
N17908016: CL1_A1.2 CL2_A1.1 R20.2 XC8.1 YC8.1
N17908018: CL1_A1.4 CL2_A1.3 R11.2 XC5.1 YC6.1
N17908020: R8.1 R17.1 R26.1 XC2.2 XC5.2 XC8.2
N17908040: R11.1 R14.2
N17908042: R14.1 R17.2
N17908062: CL1_A1.6 CL2_A1.5 R2.2 XC2.1 YC3.1
N17908092: R2.1 R5.2
N17908094: R5.1 R8.2
N17908164: R20.1 R23.2
N17908166: R23.1 R26.2
N17911015: C2.2 Q1.1(GATE) R44.1 R50.1
N17911017: Q2.3(DRAIN) R43.1 R50.2
N17911032: Q1.3(DRAIN) R42.2 RLY1.2(COIL1)
N17911094: C1.1 R35.2 R36.2 R43.2 R51.2
N17911109: D1.2(K) R33.1 RLY1.1(COIL2)
N17911126: R34.2 R35.1
N17911128: R33.2 R34.1
N17911225: C5.2 Q4.1(GATE) R62.1 R63.1
N17911227: Q5.3(DRAIN) R61.1 R63.2 R201.2
N17911239: Q4.3(DRAIN) R60.2 RLY2.2(COIL1)
N17911299: C4.1 R56.2 R57.2 R61.2 R64.2
N17911323: D2.2(K) R54.1 RLY2.1(COIL2)
N17911339: R55.2 R56.1
N17911341: R54.2 R55.1
N17913837: R37.2 R38.1
N17913950: R45.2 R46.1
N17916039: C19.1 C20.1 C21.1 C32.1 C33.1 C206.1 C207.1 C208.1 C209.1 C210.1 F7.1 F8.1 Q7.1(D) Q8.1(D) Q9.1(D) R72.2 R73.2
N17916066: L2.1 Q7.2(S) Q11.1(D)
N17916108: L3.1 Q8.2(S) Q10.1(D)
N17916243: L4.1 Q9.2(S) Q12.1(D)
N17916612: R72.1 R78.2
N17916616: R78.1 R80.2
N17916654: R77.1 R79.2
N17916656: R79.1 R81.2
N17919278: R83.1 R89.2
N17919280: R89.1 R92.2
N17919331: R84.1 R90.2
N17919333: R90.1 R93.2
N17919338: R80.1 R83.2
N17919341: R81.1 R84.2
N17920487: C10.2 C11.2 C13.2 C16.2 C17.2 C23.1 C24.1 C27.1 C28.1 C31.1 R208.1 R209.1 R210.2 R211.2 R219.1 R221.1 R222.2 R223.2 R230.1 R233.1 R234.2 R237.2
N17922701: C112.1 C113.1 R117.2 U15.1(VCC1)
N17922735: C114.1 R118.2 R119.1 U15.2(IN+)
N17922803: C115.1 C116.1 R120.1 U15.5(VCC2)
N17923309: C119.1 C120.1 R121.2 U16.1(VCC1)
N17923353: C121.1 R122.2 R123.1 U16.2(IN+)
N17923421: C122.1 C123.1 R124.1 U16.5(VCC2)
N17924447: C133.1 C134.1 R129.2 U18.1(VCC1)
N17924481: C135.1 R130.2 R131.1 U18.2(IN+)
N17924549: C136.1 C137.1 R132.1 U18.5(VCC2)
N17925295: C140.1 C141.1 R133.2 U19.1(VCC1)
N17925329: C142.1 R134.2 R136.1 U19.2(IN+)
N17925397: C143.1 C144.1 R135.1 U19.5(VCC2)
N17925494: C147.1 C148.1 R137.2 U20.1(VCC1)
N17925544: C149.1 R138.2 R139.1 U20.2(IN+)
N17925612: C150.1 C151.1 R140.1 U20.5(VCC2)
N17927817: C68.1 C69.1 R112.1 U10.1(+Vin)
N17928860: C86.1 C87.1 R114.1 U12.1(+Vin)
N17929090: C78.1 C79.1 R113.1 U11.1(+Vin)
N17930170: C104.1 C105.1 R116.1 U14.1(+Vin)
N17930400: C96.1 C97.1 R115.1 U13.1(+Vin)
N17951662: C39.1 C40.1 R98.2 R99.1 R100.1 U4.15(VCC1) U4.16(VCC)
N17951990: R99.2 R102.1 U4.14(VOC)
N17952680: C41.1 C42.1 R103.2 R104.1 R105.1 U5.15(VCC1) U5.16(VCC)
N17952780: R104.2 R109.1 U5.14(VOC)
N17953229: C43.1 C44.1 R106.2 R107.1 R108.1 U6.15(VCC1) U6.16(VCC)
N17953329: R107.2 R110.1 U6.14(VOC)
N17988040: Q6.1(GATE) R67.1 R68.2
N17988101: Q6.3(DRAIN) U2.2
N17988123: Q5.1(GATE) R64.1 R66.2 U2.4
N17988189: R65.1 U2.1
N17989219: Q3.1(GATE) R58.1 R59.2
N17989262: Q3.3(DRAIN) U1.2
N17989280: Q2.1(GATE) R51.1 R53.2 U1.4
N17989337: R52.1 U1.1
N17992674: R73.1 R77.2
N17992702: R92.1 R94.2
N18031698: CL1.4(P12) U3.1(IP1+) U3.2(IP2+) U3.3(IP3+) U3.4(IP4+)
N18031715: C204.1 C205.1 CON5.1 CON5.2 CON5.3 CON5.4 U3.5(IP1-) U3.6(IP2-) U3.7(IP3-) U3.8(IP4-)
N18031729: C37.1 C38.1 R95.2 R96.1 R97.1 U3.15(VCC1) U3.16(VCC)
N18031813: R96.2 R101.1 U3.14(VOC)
N18060364: C204.2 C205.2 CL1.3(P22) CON6.1 CON6.2 CON6.3 CON6.4 YC11.1
N18077527: C213.1 R191.2 R200.2
N18077715: C212.2 Q15.1(GATE) R198.1 R201.1
N18077724: Q15.3(DRAIN) R203.2 RLY3.2(COIL1)
N18077784: D12.2(K) R199.1 RLY3.1(COIL2)
N18077797: R200.1 R202.2
N18077799: R199.2 R202.1
N18083752: R204.2 R206.1
N18083755: R205.2 R207.1
N18083758: R204.1 R208.2
N18083761: R205.1 R209.2
N18084124: R210.1 R212.2
N18084127: R211.1 R213.2
N18084130: R213.1 R215.2
N18084133: R212.1 R214.2
N18084369: R216.2 R218.1
N18084371: R217.2 R220.1
N18084373: R216.1 R219.2
N18084375: R217.1 R221.2
N18084659: R222.1 R225.2
N18084661: R223.1 R224.2
N18084679: R224.1 R227.2
N18084681: R225.1 R226.2
N18089484: R228.2 R229.1
N18089486: R228.1 R230.2
N18089654: R231.2 R232.1
N18089656: R231.1 R233.2
N18089831: R234.1 R235.2
N18089841: R235.1 R236.2
N18090018: R237.1 R238.2
N18090028: R238.1 R239.2
N18113323: D1.1(A) R42.1
N18113324: D12.1(A) R203.1
N18113328: D2.1(A) R60.1
N18151288: R241.1 R244.2
N18151343: R240.1 R243.2
N18151366: R242.1 R245.2
N18156742: R9.1 R18.1 R27.1 XC3.2 XC6.2 XC9.2 XC10.2 XC11.2 XC12.2
N18156744: R12.1 R15.2
N18156746: R15.1 R18.2
N18156778: R3.1 R6.2
N18156780: R6.1 R9.2
N18156832: R21.1 R24.2
N18156834: R24.1 R27.2
N18158495: MT3.1 YC11.2
N18179724: D13.1(A) R258.2
N18179852: D14.1(A) R259.2
N18179938: D15.1(A) R260.2
N18180027: D16.1(A) R261.2
N18180134: D17.1(A) R262.2
N18180239: D18.1(A) R263.2
N18184240: R243.1 R264.2
N18184278: R244.1 R265.2
N18184299: R245.1 R266.2
N18188097: RV1.1 RV2.2
N18188215: RV3.1 RV4.2
N18188398: RV5.2 RV6.1
N18189276: MT2.1 YC10.2
N18202622: MT1.1 R267.2

Not connected (* = marked no-connect by the designer): J2 8 9 10; J4 3 4 7 8; J5 3; U22 5(NC); U25 5(NC); U29 5(NC)

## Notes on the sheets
sheet 1
- 3phases Input: AC 304Vac to 456Vac
- 40A trace before the Ecap.
- EMI AND Inrush limiter
- EMI AND Inrush limiter
- EMI filter, MOV and fuse
- INPUT VOLTAGE SAMPLE
- PCB Ver.: 02
- BOM Ver.: A
- Prepared by:
- Approved by:
- .
- Iris Liu
- Frank Wei
sheet 2
- VPFC and PGND 35A trace after the Ecap.
- PFC AND INVERTER
- VPFC and PGND 35A trace before the Ecap.
- RMS:2.75V
- Ioutrms: 2.65V
- RMS:1.1V
- PFC OVP UVP 725V--->1.994V
- RMS: 2.75V
- 900V--->2..476V
- PFC Output FB 725V--->1.994V
- PCB Ver.: 02
- BOM Ver.: A
- Prepared by:
- .
- Iris Liu
- Approved by:
- Frank Wei
sheet 3
- 12V--->+5V
- 6.5V--->+5V for control
- PFC power supply for gate driver
- Connect to  Control board
- Connect to  AUX power board
- PCB Ver.: 02
- BOM Ver.: A
- Prepared by:
- .
- Iris Liu
- Approved by:
- Frank Wei
sheet 4
- PCB Ver.: 02
- BOM Ver.: A
- Prepared by:
- .
- Iris Liu
- Approved by:
- Frank Wei
sheet 5
- Vab-ADC:  1.98V
- VAB Voltage Sense
- Vbc-ADC:  1.98V
- VBC Voltage Sense
- Vca-ADC:  1.98V
- PCB Ver.: 02
- BOM Ver.: A
- Prepared by:
- .
- Iris Liu
- Approved by:
- Frank Wei
- VCA Voltage Sense
